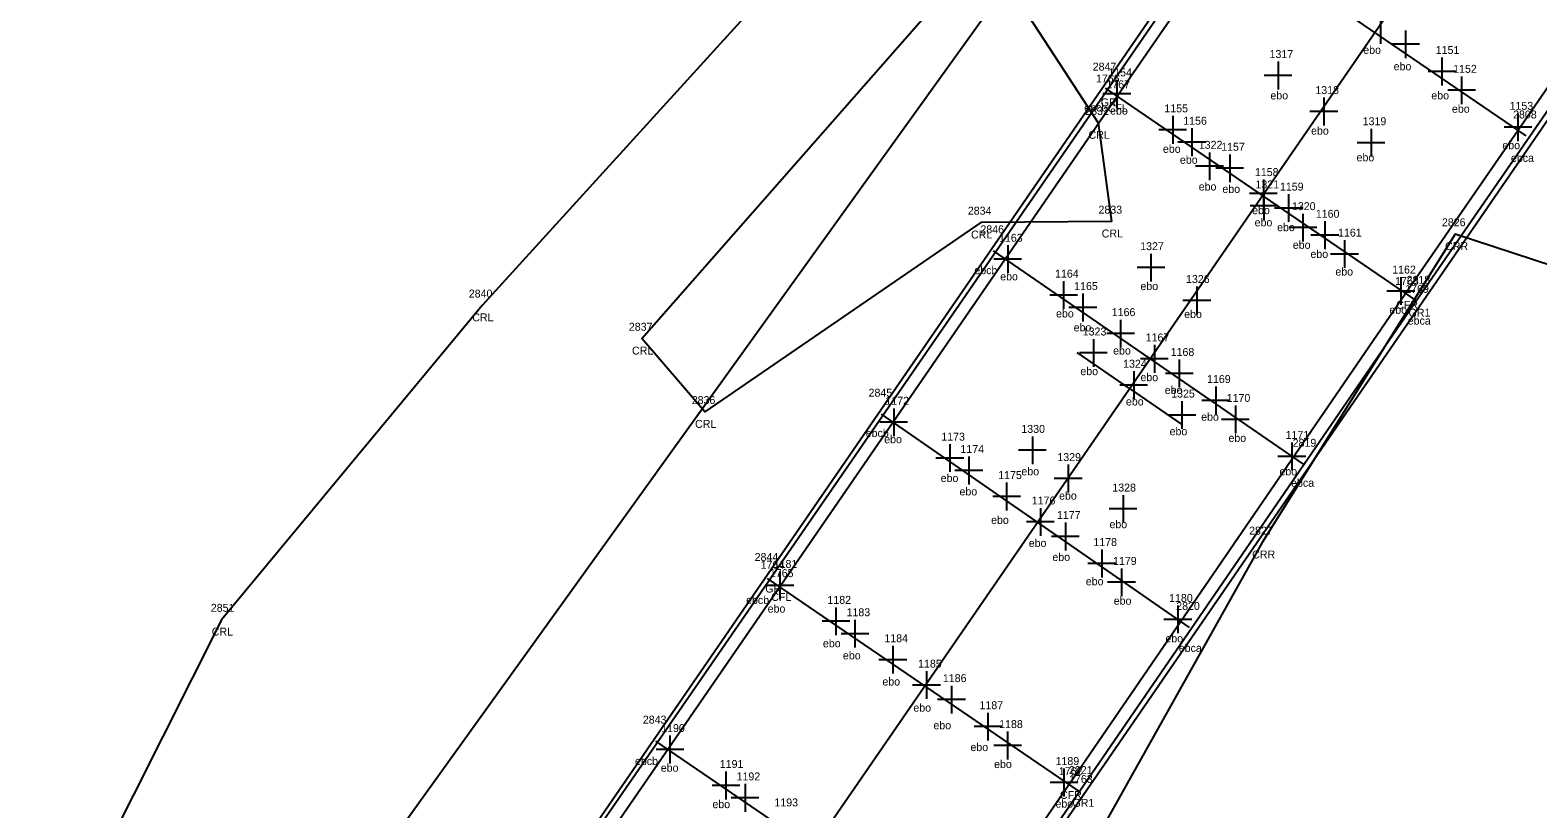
# Model space of a CAD drawing. Extents: x 2266664 to 2272542, y 716533 to 724777.
# Drawn here: x 2268915.8 to 2269105.7, y 719905.2 to 720003.3 of the extents above; entities that cross this region are included whole.
import ezdxf

# ---------------------------------------------------------------- set-up
doc = ezdxf.new("R2010")
doc.units = 0
for name, color, linetype in [('RD_EX_Bridge', 7, 'Continuous'), ('RD_EX_Conc', 7, 'Continuous'), ('RD_EX_Conc_txCode', 7, 'Continuous'), ('RD_EX_GuardRail', 7, 'Continuous'), ('RD_EX_GuardRail_txCode', 7, 'Continuous'), ('RD_EX_H2O', 7, 'Continuous'), ('RD_EX_H2O_txCode', 7, 'Continuous'), ('RD_EX_Misc', 7, 'Continuous'), ('RD_EX_Misc_txCode', 7, 'Continuous'), ('RD_EX_VEG', 7, 'Continuous'), ('RD_HC_Cl', 7, 'Continuous'), ('RD_HC_Data_Tic', 7, 'Continuous'), ('RD_SMD_Locator', 7, 'Continuous')]:
    doc.layers.add(name, color=color, linetype=linetype)

msp = doc.modelspace()

# ---------------------------------------------------------------- linework, layer by layer
at = {"layer": 'RD_EX_Bridge'}
msp.add_lwpolyline([(2269005.71, 719844.75), (2269233.07, 720175.43), (2269193.18, 720202.86), (2268965.85, 719872.44), (2269005.71, 719844.75)], dxfattribs=at)
at = {"layer": 'RD_EX_Conc'}
for points in [[(2268967.59, 719871.21), (2269010.36, 719933.37), (2269052.74, 719994.95), (2269096, 720057.76), (2269138.05, 720118.85), (2269194.93, 720201.62)], [(2269004.04, 719846.24), (2269046.75, 719908.42), (2269089.1, 719970.17), (2269131.56, 720031.81), (2269174.47, 720094.11), (2269231.14, 720176.62)]]:
    msp.add_lwpolyline(points, dxfattribs=at)
at = {"layer": 'RD_EX_GuardRail'}
for points in [[(2268966.72, 719781.34), (2268981.11, 719807.65), (2269004.56, 719845.55), (2269006.56, 719847.08), (2269048.04, 719907.43), (2269090.37, 719969.18), (2269132.94, 720030.91), (2269175.81, 720093.43), (2269231.32, 720174.06), (2269253.93, 720204.36), (2269271.7, 720223.93)], [(2268919.97, 719814.14), (2268926.75, 719820.52), (2268951.58, 719851.69), (2268966.29, 719871.68), (2268967.47, 719873.87), (2269009.19, 719934.42), (2269051.44, 719995.68), (2269094.56, 720058.42), (2269136.79, 720119.9), (2269193.57, 720202.38)]]:
    msp.add_lwpolyline(points, dxfattribs=at)
at = {"layer": 'RD_EX_H2O'}
for points in [[(2269026.84, 720028.11), (2268972.74, 719968.59), (2268939.93, 719929), (2268910.32, 719870.19), (2268897.54, 719838.49), (2268888.45, 719839.47), (2268875.86, 719855.03)], [(2269036.01, 720013.6), (2269050.34, 719991.59), (2269052.01, 719979.16), (2269035.55, 719979.03), (2269000.8, 719955.17), (2268992.86, 719964.41), (2269036.01, 720013.6)], [(2269107.58, 719973.56), (2269095.28, 719977.57), (2269070.98, 719938.72), (2269048.32, 719898.25), (2269027.3, 719869.48), (2269018.7, 719862.89), (2268974.14, 719885.31), (2268963.55, 719889.65), (2268950.25, 719883.32), (2268935.68, 719840.14)]]:
    msp.add_lwpolyline(points, dxfattribs=at)
at = {"layer": 'RD_EX_Misc'}
for p, q in [((2269104.26, 719989.95), (2269065.38, 720016.53)), ((2269085.9, 720005.07), (2269085.9, 720001.57)), ((2269089.04, 720003.24), (2269089.04, 719999.74)), ((2269090.79, 720001.49), (2269087.29, 720001.49)), ((2269072.99, 719999.31), (2269072.99, 719995.81)), ((2269093.63, 719999.82), (2269093.63, 719996.32)), ((2269074.74, 719997.56), (2269071.24, 719997.56)), ((2269095.38, 719998.07), (2269091.88, 719998.07)), ((2269096.11, 719997.45), (2269096.11, 719993.95)), ((2269054.43, 719995.25), (2269050.93, 719995.25)), ((2269090.53, 719969.12), (2269051.28, 719995.98)), ((2269052.68, 719997), (2269052.68, 719993.5)), ((2269097.86, 719995.7), (2269094.36, 719995.7)), ((2269078.75, 719994.77), (2269078.75, 719991.27)), ((2269059.73, 719992.47), (2269059.73, 719988.97)), ((2269080.5, 719993.02), (2269077, 719993.02)), ((2269103.21, 719992.79), (2269103.21, 719989.29)), ((2269061.48, 719990.72), (2269057.98, 719990.72)), ((2269062.13, 719990.91), (2269062.13, 719987.41)), ((2269084.71, 719990.85), (2269084.71, 719987.35)), ((2269104.96, 719991.04), (2269101.46, 719991.04)), ((2269063.88, 719989.16), (2269060.38, 719989.16)), ((2269064.35, 719987.88), (2269064.35, 719984.38)), ((2269066.9, 719987.63), (2269066.9, 719984.13)), ((2269086.46, 719989.1), (2269082.96, 719989.1)), ((2269066.1, 719986.13), (2269062.6, 719986.13)), ((2269068.65, 719985.88), (2269065.15, 719985.88)), ((2269071.14, 719984.44), (2269071.14, 719980.94)), ((2269072.89, 719982.69), (2269069.39, 719982.69)), ((2269071.22, 719982.89), (2269071.22, 719979.39)), ((2269074.29, 719982.61), (2269074.29, 719979.11)), ((2269072.97, 719981.14), (2269069.47, 719981.14)), ((2269076.04, 719980.86), (2269072.54, 719980.86)), ((2269078.88, 719979.19), (2269078.88, 719975.69)), ((2269038.94, 719976.17), (2269038.94, 719972.67)), ((2269080.63, 719977.44), (2269077.13, 719977.44)), ((2269081.36, 719976.82), (2269081.36, 719973.32)), ((2269076.18, 719948.59), (2269037.16, 719975.48)), ((2269040.69, 719974.42), (2269037.19, 719974.42)), ((2269056.98, 719975.11), (2269056.98, 719971.61)), ((2269083.11, 719975.07), (2269079.61, 719975.07)), ((2269058.73, 719973.36), (2269055.23, 719973.36)), ((2269045.99, 719971.65), (2269045.99, 719968.15)), ((2269062.77, 719970.97), (2269062.77, 719967.47)), ((2269088.46, 719972.16), (2269088.46, 719968.66)), ((2269047.74, 719969.9), (2269044.24, 719969.9)), ((2269048.4, 719970.08), (2269048.4, 719966.58)), ((2269064.52, 719969.22), (2269061.02, 719969.22)), ((2269090.21, 719970.41), (2269086.71, 719970.41)), ((2269050.15, 719968.33), (2269046.65, 719968.33)), ((2269053.16, 719966.8), (2269053.16, 719963.3)), ((2269054.91, 719965.05), (2269051.41, 719965.05)), ((2269049.74, 719964.36), (2269049.74, 719960.86)), ((2269057.41, 719963.61), (2269057.41, 719960.11)), ((2269051.49, 719962.61), (2269047.99, 719962.61)), ((2269059.16, 719961.86), (2269055.66, 719961.86)), ((2269060.55, 719961.78), (2269060.55, 719958.28)), ((2269054.82, 719960.3), (2269054.82, 719956.8)), ((2269062.3, 719960.03), (2269058.8, 719960.03)), ((2269056.57, 719958.55), (2269053.07, 719958.55)), ((2269065.14, 719958.37), (2269065.14, 719954.87)), ((2269024.59, 719955.63), (2269024.59, 719952.13)), ((2269060.87, 719956.54), (2269060.87, 719953.04)), ((2269066.89, 719956.62), (2269063.39, 719956.62)), ((2269067.62, 719955.99), (2269067.62, 719952.49)), ((2269026.34, 719953.88), (2269022.84, 719953.88)), ((2269061.84, 719928.03), (2269023.05, 719954.9)), ((2269062.62, 719954.79), (2269059.12, 719954.79)), ((2269069.37, 719954.24), (2269065.87, 719954.24)), ((2269042.05, 719952.09), (2269042.05, 719948.59)), ((2269031.65, 719951.11), (2269031.65, 719947.61)), ((2269043.8, 719950.34), (2269040.3, 719950.34)), ((2269076.47, 719949.58), (2269072.97, 719949.58)), ((2269074.72, 719951.33), (2269074.72, 719947.83)), ((2269033.4, 719949.36), (2269029.9, 719949.36)), ((2269035.8, 719947.8), (2269032.3, 719947.8)), ((2269034.05, 719949.55), (2269034.05, 719946.05)), ((2269046.55, 719948.54), (2269046.55, 719945.04)), ((2269038.81, 719946.27), (2269038.81, 719942.77)), ((2269048.3, 719946.79), (2269044.8, 719946.79)), ((2269040.56, 719944.52), (2269037.06, 719944.52)), ((2269053.47, 719944.7), (2269053.47, 719941.2)), ((2269043.06, 719943.07), (2269043.06, 719939.57)), ((2269055.22, 719942.95), (2269051.72, 719942.95)), ((2269044.81, 719941.32), (2269041.31, 719941.32)), ((2269046.21, 719941.24), (2269046.21, 719937.74)), ((2269047.96, 719939.49), (2269044.46, 719939.49)), ((2269050.79, 719937.83), (2269050.79, 719934.33)), ((2269010.25, 719935.08), (2269010.25, 719931.58)), ((2269052.54, 719936.08), (2269049.04, 719936.08)), ((2269053.27, 719935.46), (2269053.27, 719931.96)), ((2269012, 719933.33), (2269008.5, 719933.33)), ((2269047.99, 719907.35), (2269008.7, 719934.2)), ((2269055.02, 719933.71), (2269051.52, 719933.71)), ((2269060.37, 719930.79), (2269060.37, 719927.29)), ((2269019.06, 719928.8), (2269015.56, 719928.8)), ((2269017.31, 719930.55), (2269017.31, 719927.05)), ((2269019.71, 719928.99), (2269019.71, 719925.49)), ((2269062.12, 719929.04), (2269058.62, 719929.04)), ((2269021.46, 719927.24), (2269017.96, 719927.24)), ((2269024.47, 719925.71), (2269024.47, 719922.21)), ((2269026.22, 719923.96), (2269022.72, 719923.96)), ((2269028.72, 719922.52), (2269028.72, 719919.02)), ((2269030.47, 719920.77), (2269026.97, 719920.77)), ((2269031.87, 719920.69), (2269031.87, 719917.19)), ((2269033.62, 719918.94), (2269030.12, 719918.94)), ((2269038.2, 719915.53), (2269034.7, 719915.53)), ((2269036.45, 719917.28), (2269036.45, 719913.78)), ((2269033.91, 719886.87), (2268994.62, 719913.71)), ((2268996.41, 719914.4), (2268996.41, 719910.9)), ((2269038.93, 719914.9), (2269038.93, 719911.4)), ((2268998.16, 719912.65), (2268994.66, 719912.65)), ((2269040.68, 719913.15), (2269037.18, 719913.15)), ((2269003.46, 719909.87), (2269003.46, 719906.37)), ((2269046.03, 719910.24), (2269046.03, 719906.74)), ((2269005.21, 719908.12), (2269001.71, 719908.12)), ((2269005.87, 719908.31), (2269005.87, 719904.81)), ((2269047.78, 719908.49), (2269044.28, 719908.49)), ((2269007.62, 719906.56), (2269004.12, 719906.56))]:
    msp.add_line(p, q, dxfattribs=at)
at = {"layer": 'RD_EX_Misc_txCode'}
for p, q in [((2269076.13, 719980.15), (2269076.13, 719976.65)), ((2269077.88, 719978.4), (2269074.38, 719978.4))]:
    msp.add_line(p, q, dxfattribs=at)
at = {"layer": 'RD_EX_VEG'}
msp.add_lwpolyline([(2268819.78, 719716.8), (2268871.54, 719776.21), (2269193.85, 720224.65), (2269408.57, 720538.5), (2269589.67, 720791.77), (2270047.56, 721479.8), (2270363.13, 721951.09), (2270746.65, 722498.38), (2270919.94, 722752.82), (2271017.26, 722923.37)], dxfattribs=at)
at = {"layer": 'RD_HC_Cl'}
msp.add_line((2267342.91, 717471.2), (2272360.46, 724762.59), dxfattribs=at)
at = {"layer": 'RD_HC_Data_Tic'}
for q in [(2269047.7, 719962.67), (2269060.88, 719953.6)]:
    msp.add_line((2269054.29, 719958.14), q, dxfattribs=at)
at = {"layer": 'RD_SMD_Locator'}
for centre in [(2269051.44, 719995.68), (2269052.74, 719994.95), (2269050.34, 719991.59), (2269035.55, 719979.03), (2269052.01, 719979.16), (2269095.28, 719977.57), (2268972.74, 719968.59), (2269089.1, 719970.17), (2269090.37, 719969.18), (2268992.86, 719964.41), (2269000.8, 719955.17), (2269070.98, 719938.72), (2269009.19, 719934.42), (2269010.36, 719933.37), (2268939.93, 719929), (2269046.75, 719908.42), (2269048.04, 719907.43)]:
    msp.add_circle(centre, 0.001, dxfattribs=at)

# ---------------------------------------------------------------- texts
at = {"layer": 'RD_EX_Conc_txCode'}
for s, p in [('1767', (2269051.37, 719995.95)), ('CFL', (2269051.54, 719992.95)), ('1768', (2269087.73, 719971.17)), ('CFR', (2269087.87, 719968.17)), ('1765', (2269008.99, 719934.37)), ('CFL', (2269009.16, 719931.37)), ('1762', (2269045.38, 719909.42)), ('CFR', (2269045.53, 719906.42))]:
    msp.add_text(s, height=1, dxfattribs=at).set_placement(p)
at = {"layer": 'RD_EX_GuardRail_txCode'}
for s, p in [('1766', (2269050.05, 719996.68)), ('GR', (2269050.66, 719993.68)), ('1769', (2269089, 719970.18)), ('GR1', (2269089.43, 719967.18)), ('1764', (2269007.82, 719935.42)), ('GR', (2269008.41, 719932.42)), ('1763', (2269046.67, 719908.43)), ('GR1', (2269047.1, 719905.43))]:
    msp.add_text(s, height=1, dxfattribs=at).set_placement(p)
at = {"layer": 'RD_EX_H2O_txCode'}
for s, p in [('2832', (2269048.71, 719992.59)), ('CRL', (2269049.12, 719989.59)), ('2834', (2269033.92, 719980.03)), ('2833', (2269050.38, 719980.16)), ('CRL', (2269050.78, 719977.16)), ('2826', (2269093.63, 719978.57)), ('CRL', (2269034.32, 719977.03)), ('CRR', (2269094.03, 719975.57)), ('2840', (2268971.07, 719969.59)), ('CRL', (2268971.51, 719966.59)), ('2837', (2268991.23, 719965.41)), ('CRL', (2268991.63, 719962.41)), ('2836', (2268999.15, 719956.17)), ('CRL', (2268999.57, 719953.17)), ('2827', (2269069.35, 719939.72)), ('CRR', (2269069.73, 719936.72)), ('2851', (2268938.58, 719930)), ('CRL', (2268938.7, 719927))]:
    msp.add_text(s, height=1, dxfattribs=at).set_placement(p)
at = {"layer": 'RD_EX_Misc'}
msp.add_text('ebo', height=1, dxfattribs=at).set_placement((2269072.87, 719977.95))
at = {"layer": 'RD_EX_Misc_txCode'}
for s, p in [('ebo', (2269083.72, 720000.29)), ('1151', (2269092.85, 720000.27)), ('2847', (2269049.65, 719998.18)), ('1317', (2269071.92, 719999.76)), ('ebo', (2269087.55, 719998.22)), ('1154', (2269051.61, 719997.45)), ('1152', (2269095.05, 719997.9)), ('ebo', (2269072.03, 719994.55)), ('1318', (2269077.69, 719995.22)), ('ebo', (2269092.29, 719994.55)), ('ebcb', (2269048.58, 719993.03)), ('ebo', (2269051.84, 719992.64)), ('1155', (2269058.67, 719992.92)), ('ebo', (2269094.89, 719992.87)), ('1153', (2269102.15, 719993.24)), ('1156', (2269061.05, 719991.36)), ('1319', (2269083.65, 719991.3)), ('2808', (2269102.59, 719992.15)), ('ebo', (2269077.15, 719990.11)), ('ebo', (2269058.49, 719987.82)), ('1322', (2269063.01, 719988.33)), ('1157', (2269065.83, 719988.08)), ('ebo', (2269082.88, 719986.75)), ('ebo', (2269101.24, 719988.28)), ('ebca', (2269102.32, 719986.68)), ('ebo', (2269060.63, 719986.44)), ('1158', (2269070.08, 719984.89)), ('ebo', (2269063, 719983.07)), ('ebo', (2269065.98, 719982.77)), ('1321', (2269070.15, 719983.34)), ('1159', (2269073.23, 719983.06)), ('ebo', (2269069.73, 719980.09)), ('1320', (2269074.74, 719980.6)), ('1160', (2269077.75, 719979.64)), ('2846', (2269035.5, 719977.68)), ('ebo', (2269070.04, 719978.56)), ('1161', (2269080.55, 719977.27)), ('1163', (2269037.85, 719976.62)), ('1327', (2269055.63, 719975.56)), ('ebo', (2269074.85, 719975.73)), ('ebo', (2269077.07, 719974.58)), ('ebcb', (2269034.74, 719972.53)), ('ebo', (2269038, 719971.75)), ('1164', (2269044.91, 719972.1)), ('1326', (2269061.4, 719971.42)), ('ebo', (2269080.21, 719972.36)), ('1162', (2269087.37, 719972.61)), ('1165', (2269047.31, 719970.53)), ('ebo', (2269055.66, 719970.53)), ('2818', (2269089.18, 719971.32)), ('ebo', (2269087.01, 719967.54)), ('ebo', (2269045.03, 719967.08)), ('1166', (2269052.05, 719967.25)), ('ebo', (2269061.17, 719967.01)), ('ebca', (2269089.32, 719966.18)), ('ebo', (2269047.25, 719965.32)), ('1323', (2269048.39, 719964.81)), ('1167', (2269056.32, 719964.06)), ('ebo', (2269052.22, 719962.41)), ('1168', (2269059.47, 719962.23)), ('1324', (2269053.48, 719960.75)), ('ebo', (2269048.09, 719959.81)), ('ebo', (2269055.66, 719959.05)), ('1169', (2269064.05, 719958.82)), ('2845', (2269021.42, 719957.1)), ('ebo', (2269058.72, 719957.44)), ('1325', (2269059.53, 719956.99)), ('1170', (2269066.52, 719956.44)), ('1172', (2269023.53, 719956.08)), ('ebo', (2269053.83, 719955.99)), ('1330', (2269040.66, 719952.54)), ('ebo', (2269063.31, 719954.07)), ('ebcb', (2269021.06, 719952.02)), ('ebo', (2269023.39, 719951.24)), ('1173', (2269030.58, 719951.56)), ('ebo', (2269059.33, 719952.24)), ('ebo', (2269066.75, 719951.4)), ('1171', (2269073.94, 719951.78)), ('2819', (2269074.83, 719950.79)), ('1174', (2269032.99, 719950)), ('1329', (2269045.2, 719948.99)), ('1175', (2269037.75, 719946.72)), ('ebo', (2269040.67, 719947.19)), ('ebo', (2269073.17, 719947.19)), ('ebo', (2269030.5, 719946.35)), ('1328', (2269052.12, 719945.15)), ('ebca', (2269074.64, 719945.75)), ('ebo', (2269032.87, 719944.66)), ('1176', (2269041.97, 719943.52)), ('ebo', (2269045.41, 719944.13)), ('ebo', (2269036.85, 719941.07)), ('1177', (2269045.14, 719941.69)), ('ebo', (2269051.76, 719940.53)), ('ebo', (2269041.59, 719938.16)), ('1178', (2269049.73, 719938.28)), ('2844', (2269007.07, 719936.4)), ('1181', (2269009.47, 719935.53)), ('ebo', (2269044.57, 719936.4)), ('1179', (2269052.21, 719935.91)), ('ebo', (2269048.78, 719933.34)), ('ebcb', (2269005.99, 719930.98)), ('ebo', (2269008.71, 719929.9)), ('1182', (2269016.24, 719931)), ('ebo', (2269052.3, 719930.89)), ('1180', (2269059.27, 719931.24)), ('2820', (2269060.17, 719930.23)), ('1183', (2269018.65, 719929.44)), ('1184', (2269023.41, 719926.16)), ('ebo', (2269058.8, 719926.15)), ('ebo', (2269015.67, 719925.53)), ('ebo', (2269018.19, 719924)), ('ebca', (2269060.49, 719924.94)), ('1185', (2269027.66, 719922.97)), ('ebo', (2269023.16, 719920.71)), ('1186', (2269030.78, 719921.14)), ('ebo', (2269027.06, 719917.42)), ('1187', (2269035.39, 719917.73)), ('2843', (2268992.99, 719915.91)), ('1190', (2268995.3, 719914.85)), ('ebo', (2269029.59, 719915.2)), ('1188', (2269037.87, 719915.35)), ('ebo', (2269034.25, 719912.45)), ('ebcb', (2268992, 719910.7)), ('1189', (2269044.97, 719910.69)), ('ebo', (2268995.25, 719909.85)), ('1191', (2269002.68, 719910.32)), ('1192', (2269004.8, 719908.76)), ('ebo', (2269037.23, 719910.31)), ('2821', (2269046.65, 719909.55)), ('ebo', (2269001.75, 719905.26)), ('1193', (2269009.56, 719905.48)), ('ebo', (2269044.96, 719905.33))]:
    msp.add_text(s, height=1, dxfattribs=at).set_placement(p)

doc.saveas('drawing.dxf')
